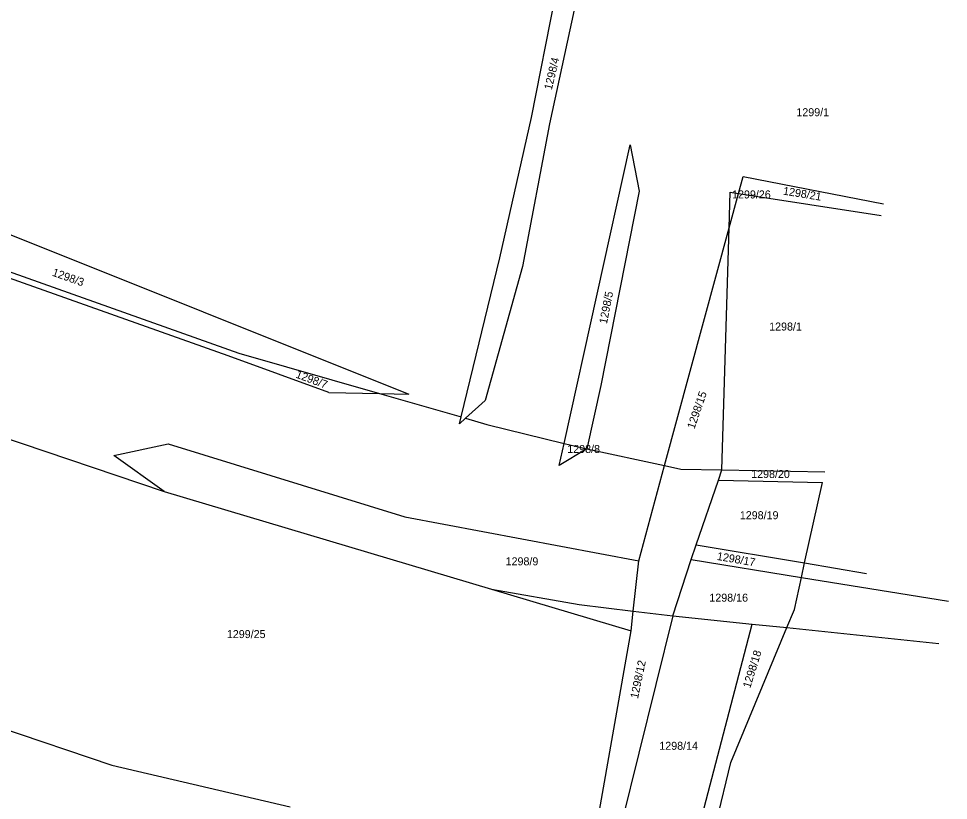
# Model space of a CAD drawing. Extents: x -563148 to -561712, y -1182311 to -1179502.
# Drawn here: x -562032.9 to -561858.6, y -1181163.6 to -1181017.2 of the extents above; entities that cross this region are included whole.
import ezdxf

# ---------------------------------------------------------------- set-up
doc = ezdxf.new("R2010")
doc.units = 0
for name, color, linetype in [('Vrstva 55', 7, 'Continuous'), ('Vrstva 56', 7, 'Continuous'), ('Vrstva 57', 7, 'Continuous')]:
    doc.layers.add(name, color=color, linetype=linetype)

msp = doc.modelspace()

# ---------------------------------------------------------------- linework, layer by layer
at = {"layer": 'Vrstva 55'}
for p, q in [((-561936.8, -1181035.7), (-561930.3, -1181002.6)), ((-561927, -1181007.2), (-561933.4, -1181036.9)), ((-561942.7, -1181062), (-561936.8, -1181035.7)), ((-561933.4, -1181036.9), (-561938.5, -1181063.6)), ((-561930.68, -1181096.75), (-561918.3, -1181040.8)), ((-561918.3, -1181040.8), (-561916.6, -1181049.5)), ((-561898, -1181049.93), (-561897.14, -1181046.76)), ((-561897.14, -1181046.76), (-561870.78, -1181051.85)), ((-561916.6, -1181049.5), (-561923.8, -1181085.9)), ((-561899.76, -1181056.4), (-561899.56, -1181049.69)), ((-561899.76, -1181056.4), (-561898, -1181049.93)), ((-561899.56, -1181049.69), (-561898, -1181049.93)), ((-561898, -1181049.93), (-561871.27, -1181054.09)), ((-562043.02, -1181054.22), (-561959.77, -1181087.52)), ((-561911.85, -1181100.91), (-561899.76, -1181056.4)), ((-561901.1, -1181101.7), (-561899.76, -1181056.4)), ((-561949.98, -1181091.8), (-561942.7, -1181062)), ((-562037.7, -1181063.53), (-561991.67, -1181079.84)), ((-561938.5, -1181063.6), (-561945.5, -1181088.7)), ((-561993.67, -1181080.36), (-562036.84, -1181065.04)), ((-561974.79, -1181087.21), (-561993.67, -1181080.36)), ((-561991.67, -1181079.84), (-561965.29, -1181087.41)), ((-561923.8, -1181085.9), (-561926.4, -1181097.8)), ((-561974.79, -1181087.21), (-561965.29, -1181087.41)), ((-561965.29, -1181087.41), (-561959.77, -1181087.52)), ((-561965.29, -1181087.41), (-561949.98, -1181091.8)), ((-561949.14, -1181092.04), (-561945.5, -1181088.7)), ((-561950.3, -1181093.1), (-561949.98, -1181091.8)), ((-562042.39, -1181093.4), (-562005.67, -1181105.77)), ((-561950.3, -1181093.1), (-561949.14, -1181092.04)), ((-561949.14, -1181092.04), (-561945.13, -1181093.19)), ((-561945.13, -1181093.19), (-561930.68, -1181096.75)), ((-562015.1, -1181099.03), (-562004.88, -1181096.81)), ((-562004.88, -1181096.81), (-561960.56, -1181110.54)), ((-561931.6, -1181100.9), (-561930.68, -1181096.75)), ((-561930.68, -1181096.75), (-561926.4, -1181097.8)), ((-561926.4, -1181097.8), (-561931.6, -1181100.9)), ((-561926.4, -1181097.8), (-561911.85, -1181100.91)), ((-562005.67, -1181105.77), (-562015.1, -1181099.03)), ((-561916.69, -1181118.74), (-561911.85, -1181100.91)), ((-561911.85, -1181100.91), (-561908.78, -1181101.56)), ((-561908.78, -1181101.56), (-561901.1, -1181101.7)), ((-561901.76, -1181103.63), (-561901.1, -1181101.7)), ((-561901.1, -1181101.7), (-561881.83, -1181102.06)), ((-561905.91, -1181115.77), (-561901.76, -1181103.63)), ((-561901.76, -1181103.63), (-561882.27, -1181104.06)), ((-561885.59, -1181119.16), (-561882.27, -1181104.06)), ((-562005.67, -1181105.77), (-561944.29, -1181124.06)), ((-561960.56, -1181110.54), (-561916.69, -1181118.74)), ((-561906.84, -1181118.49), (-561905.91, -1181115.77)), ((-561905.91, -1181115.77), (-561885.59, -1181119.16)), ((-561910.28, -1181129.09), (-561906.84, -1181118.49)), ((-561906.84, -1181118.49), (-561886.19, -1181121.86)), ((-561886.19, -1181121.86), (-561885.59, -1181119.16)), ((-561885.59, -1181119.16), (-561874.01, -1181121.1)), ((-561887.51, -1181127.87), (-561886.19, -1181121.86)), ((-561886.19, -1181121.86), (-561858.64, -1181126.34)), ((-561944.29, -1181124.06), (-561927.87, -1181126.93)), ((-561944.29, -1181124.06), (-561918.1, -1181131.86)), ((-561927.87, -1181126.93), (-561917.7, -1181128.18)), ((-561917.7, -1181128.18), (-561910.28, -1181129.09)), ((-561888.93, -1181131.27), (-561887.51, -1181127.87)), ((-561910.28, -1181129.09), (-561921.71, -1181175.02)), ((-561910.28, -1181129.09), (-561895.44, -1181130.59)), ((-561925.64, -1181174.69), (-561918.1, -1181131.86)), ((-561907.36, -1181176.23), (-561895.44, -1181130.59)), ((-561899.45, -1181156.54), (-561888.93, -1181131.27)), ((-561895.44, -1181130.59), (-561888.93, -1181131.27)), ((-561888.93, -1181131.27), (-561860.46, -1181134.24)), ((-562055.47, -1181143.5), (-562015.47, -1181157.02)), ((-562015.47, -1181157.02), (-561982, -1181164.87)), ((-561904.23, -1181176.49), (-561899.45, -1181156.54))]:
    msp.add_line(p, q, dxfattribs=at)
at = {"layer": 'Vrstva 56'}
for p, q in [((-561917.7, -1181128.18), (-561916.69, -1181118.74)), ((-561918.1, -1181131.86), (-561917.7, -1181128.18))]:
    msp.add_line(p, q, dxfattribs=at)

# ---------------------------------------------------------------- texts
at = {"layer": 'Vrstva 57'}
for s, rotation, p in [('1298/4', 76.4977, (-561932.99, -1181030.63)), ('1298/21', 350.7461, (-561889.71, -1181050.13)), ('1298/3', 340.502, (-562026.76, -1181065.31)), ('1298/5', 78.7353, (-561922.66, -1181074.46)), ('1298/7', 339.5184, (-561981.11, -1181084.39)), ('1298/15', 71.0394, (-561906.25, -1181094.17)), ('1298/17', 350.225, (-561902.11, -1181118.57)), ('1298/18', 72.7803, (-561895.79, -1181142.71)), ('1298/12', 78.1255, (-561916.83, -1181144.66))]:
    msp.add_text(s, height=1.5, rotation=rotation, dxfattribs=at).set_placement(p)
for s, p in [('1299/1', (-561887.14, -1181035.46)), ('1299/26', (-561899.19, -1181050.86)), ('1298/1', (-561892.24, -1181075.61)), ('1298/8', (-561930.08, -1181098.55)), ('1298/20', (-561895.61, -1181103.24)), ('1298/19', (-561897.74, -1181110.96)), ('1298/9', (-561941.64, -1181119.6)), ('1298/16', (-561903.45, -1181126.41)), ('1299/25', (-561993.89, -1181133.23)), ('1298/14', (-561912.83, -1181154.16))]:
    msp.add_text(s, height=1.5, dxfattribs=at).set_placement(p)

doc.saveas('drawing.dxf')
